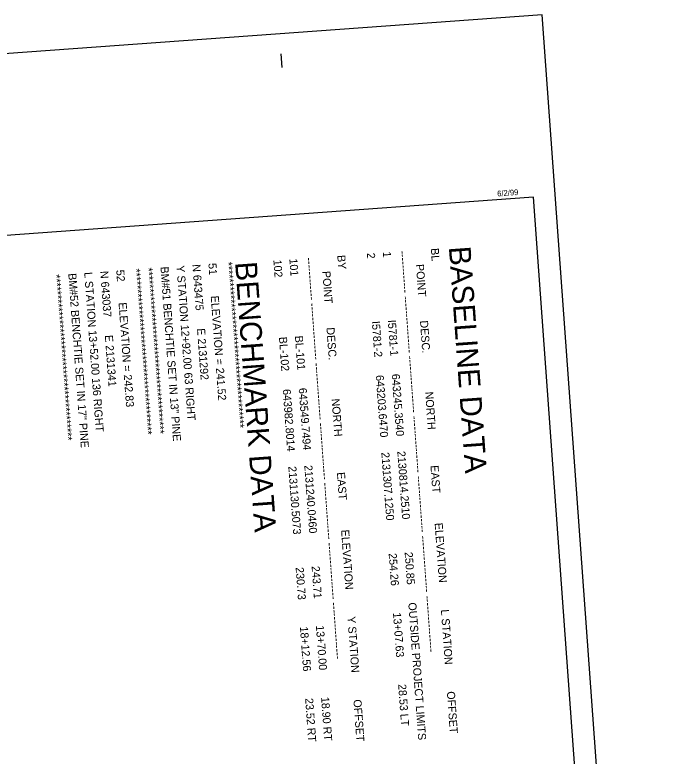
# Model space of a CAD drawing. Extents: x 2130621 to 2131998, y 642516 to 644503.
# Drawn here: x 2131307 to 2131993, y 643732 to 644503 of the extents above; entities that cross this region are included whole.
import ezdxf

# ---------------------------------------------------------------- set-up
doc = ezdxf.new("R2010")
doc.units = 0
for name, color, linetype in [('CTL Sheet Border CELL', 7, 'Continuous'), ('Default', 7, 'Continuous'), ('Sheet Plot Border Outside CELL', 7, 'Continuous')]:
    doc.layers.add(name, color=color, linetype=linetype)

msp = doc.modelspace()

# ---------------------------------------------------------------- linework, layer by layer
at = {"layer": 'CTL Sheet Border CELL'}
msp.add_line((2131583.31, 644462.47), (2131584.33, 644448.38), dxfattribs=at)
msp.add_lwpolyline([(2131968.81, 642621.99), (2131846.3, 644313.22), (2130662.45, 644227.46), (2130784.96, 642536.24)], close=True, dxfattribs=at)
at = {"layer": 'Sheet Plot Border Outside CELL'}
msp.add_lwpolyline([(2130620.63, 644413.7), (2130758.12, 642515.65), (2131992.67, 642605.07), (2131855.18, 644503.13)], close=True, dxfattribs=at)

# ---------------------------------------------------------------- texts
at = {"layer": 'CTL Sheet Border CELL'}
for s, height, rotation, p in [('6/2/99', 5.935, 4.14306, (2131808.75, 644314.05)), ('BASELINE DATA', 22.6087, 274.14306, (2131758.19, 644261.56)), ('BENCHMARK DATA', 22.6087, 274.14306, (2131535.82, 644245.53))]:
    msp.add_text(s, height=height, rotation=rotation, dxfattribs=at).set_placement(p)
at = {"layer": 'Default'}
for s, height, p in [('BL', 8.333, (2131739.44, 644260.02)), ('BY', 8.333, (2131642.12, 644252.83)), ('2                     I5781-2      643203.6470     2131307.1250           254.26         13+07.63         28.53 LT', 8.33333, (2131672.95, 644255.2)), ('1                     I5781-1      643245.3540     2130814.2510           250.85      OUTSIDE PROJECT LIMITS                 ', 8.33333, (2131689.57, 644256.41)), ('------------ ---------------- ---------------- ---------------- ---------------- ---------------- ----------------', 8.33333, (2131706.19, 644257.61)), ('51       ELEVATION = 241.52', 8.3333, (2131508.03, 644244.46)), ('****************************************', 8.3333, (2131524.65, 644245.66)), ('102                    BL-102      643982.8014     2131130.5073           230.73         18+12.56         23.52 RT', 8.33333, (2131575.63, 644248.01)), ('101                    BL-101      643549.7494     2131240.0460           243.71         13+70.00         18.90 RT', 8.33333, (2131592.25, 644249.22)), ('------------ ---------------- ---------------- ---------------- ---------------- ---------------- ----------------', 8.33333, (2131608.88, 644250.42)), ('     POINT        DESC.             NORTH            EAST          ELEVATION         L STATION         OFFSET', 8.33333, (2131722.82, 644258.82)), ('N 643037      E 2131341', 8.3333, (2131395.48, 644236.3)), ('52       ELEVATION = 242.83', 8.3333, (2131412.11, 644237.51)), ('****************************************', 8.3333, (2131428.73, 644238.71)), ('****************************************', 8.3333, (2131441.53, 644239.64)), ('BM#51 BENCHTIE SET IN 13" PINE', 8.3333, (2131458.16, 644240.84)), ('Y STATION 12+92.00 63 RIGHT', 8.3333, (2131474.78, 644242.05)), ('N 643475      E 2131292', 8.3333, (2131491.4, 644243.25)), ('     POINT        DESC.             NORTH            EAST          ELEVATION         Y STATION         OFFSET', 8.33333, (2131625.5, 644251.63)), ('****************************************', 8.3333, (2131345.61, 644232.69)), ('BM#52 BENCHTIE SET IN 17" PINE', 8.3333, (2131362.24, 644233.9)), ('L STATION 13+52.00 136 RIGHT', 8.3333, (2131378.86, 644235.1))]:
    msp.add_text(s, height=height, rotation=274.14306, dxfattribs=at).set_placement(p)

doc.saveas('drawing.dxf')
